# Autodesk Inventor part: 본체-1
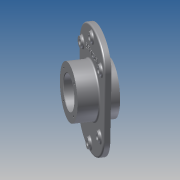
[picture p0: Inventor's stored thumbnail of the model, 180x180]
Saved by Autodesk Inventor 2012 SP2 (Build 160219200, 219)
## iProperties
Created: 2015-02
Part Number: 본체-1
Material: Default
Document SubType Name: Modeling
Designer: Administrator
Density: 1 g/cm^3
Author: Administrator
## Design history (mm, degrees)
sketch "스케치1"
  geometry: L1 (-70, 60)-(70, 60); L2 (70, 60)-(70, -60); L3 (70, -60)-(-70, -60); L4 (-70, -60)-(-70, 60); L5 (-70, 0)-(70, 0); L6 (0, 60)-(0, 110); L7 (0, -60)-(0, -110); 1 further point; 4 other entities
  constraints: 15 end point, 4 midpoint, 3 horizontal, 2 parallel, 2 vertical, 1 horizontal alignment, 1 perpendicular, 1 vertical alignment, 18 other
  dimensions: "d10" = 120 distance of L1.end L2.end; "d11" = 140 distance of L1.start L1.end; "d16" = 50 distance of L6.start L6.end
extrude "돌출1" new body sketch "스케치1" distance "d17" = 12; taper "d18" = 0 deg
sketch "스케치2"
  geometry: C1 r 50 at (0, 0); 1 further point
  constraints: 1 centre point, 1 coincident
  dimensions: "d19" = 100 diameter of C1
extrude "돌출2" join sketch "스케치2" distance "d20" = 37; taper "d22" = 0 deg; dims "d21" = 33, "d23" = 0
hole "구멍1" diameter "d26" = 62; stored, may be unused: countersink angle "d30" = 90 deg, drill point angle "d32" = 0 deg; dims "d27" = 6, "d28" = 4, "d29" = 2, "d31" = 22, "d44" = 10, "d45" = 10
hole "구멍2" diameter "d35" = 62; stored, may be unused: countersink angle "d39" = 90 deg, drill point angle "d41" = 0 deg; dims "d36" = 6, "d37" = 4, "d38" = 2, "d40" = 22, "d42" = 10, "d43" = 10
hole "구멍3" diameter "d48" = 45; stored, may be unused: countersink angle "d52" = 90 deg, drill point angle "d54" = 118 deg; dims "d46" = 10, "d47" = 10, "d49" = 6, "d50" = 4, "d51" = 2, "d53" = 22
sketch "스케치3"
  geometry: L1 (60, -70)-(-60, -70) reference; L2 (-60, 70)-(60, 70) reference; L3 (60, -53)-(-60, -53); L4 (-60, 53)-(60, 53); C1 r 50 at (0, 0) reference; C2 r 10 at (-57.146, 53); C3 r 10 at (60, 53); C4 r 10 at (-57.146, -53); C5 r 10 at (60, -53); C6 r 10 at (93, 0); C7 r 10 at (-93, 0); 8 further points; 2 other entities
  constraints: 8 coincident, 6 centre point, 4 end point, 3 horizontal alignment, 3 parallel, 2 point on line, 1 vertical alignment, 10 other
  dimensions: "d55" = 17 distance between parallel lines of L2 L4; "d56" = 20 diameter of C2; "d57" = 20 diameter of C3; "d58" = 20 diameter of C4; "d59" = 20 diameter of C5; "d60" = 20 diameter of C6; "d61" = 20 diameter of C7
extrude "돌출3" join sketch "스케치3" distance "d62" = 5; taper "d63" = 0 deg
hole "구멍4" diameter "d66" = 11; stored, may be unused: countersink angle "d70" = 90 deg, drill point angle "d72" = 118 deg; dims "d64" = 10, "d65" = 10, "d67" = 6, "d68" = 4, "d69" = 2, "d71" = 22
hole "구멍5" diameter "d75" = 11; stored, may be unused: countersink angle "d79" = 90 deg, drill point angle "d81" = 118 deg; dims "d73" = 10, "d74" = 10, "d76" = 6, "d77" = 4, "d78" = 2, "d80" = 22
hole "구멍6" diameter "d84" = 11; stored, may be unused: countersink angle "d88" = 90 deg, drill point angle "d90" = 118 deg; dims "d82" = 10, "d83" = 10, "d85" = 6, "d86" = 4, "d87" = 2, "d89" = 22
hole "구멍7" diameter "d93" = 11; stored, may be unused: countersink angle "d97" = 90 deg, drill point angle "d99" = 118 deg; dims "d91" = 10, "d92" = 10, "d94" = 6, "d95" = 4, "d96" = 2, "d98" = 22
hole "구멍8" diameter "d102" = 11; stored, may be unused: countersink angle "d106" = 90 deg, drill point angle "d108" = 118 deg; dims "d100" = 10, "d101" = 10, "d103" = 6, "d104" = 4, "d105" = 2, "d107" = 22
hole "구멍9" diameter "d111" = 11; stored, may be unused: countersink angle "d115" = 90 deg, drill point angle "d117" = 118 deg; dims "d109" = 10, "d110" = 10, "d112" = 6, "d113" = 4, "d114" = 2, "d116" = 22
sketch "스케치4"
  geometry: L1 (0, 0)-(41, 0); L2 (0, 0)-(28.991, -28.991); L3 (0, 0)-(28.991, 28.991); L4 (0, 0)-(-28.991, 28.991); L5 (0, 0)-(-28.991, -28.991); C1 r 31 at (0, 0) reference; A1 r 41 centre (0, 0) between (41, 0) and (28.991, -28.991); 4 further points
  constraints: 10 end point, 5 coincident, 2 point on circle, 1 centre point, 1 horizontal, 17 other
  dimensions: "d118" = 82 diameter of A1; "d119" = 45 deg angle of L1 L2; "d122" = 360 deg dimension on C1.centre L2.end (derived)
hole "구멍10" sketch "스케치4" at (28.991, -28.991), (28.991, 28.991), (-28.991, 28.991), (-28.991, -28.991) diameter "d124" = 4.917; stored, may be unused: countersink angle "d128" = 90 deg, drill point angle "d130" = 118 deg; dims "d125" = 10, "d126" = 4, "d127" = 2, "d129" = 13
sketch "스케치5"
  geometry: L1 (0, 0)-(-41, 0); L2 (0, 0)-(-28.991, -28.991); L3 (0, 0)-(28.991, -28.991); L4 (0, 0)-(28.991, 28.991); L5 (0, 0)-(-28.991, 28.991); C1 r 31 at (0, 0) reference; A1 r 41 centre (0, 0) between (-41, 0) and (-28.991, -28.991); 4 further points
  constraints: 10 end point, 5 coincident, 2 point on circle, 1 centre point, 1 horizontal, 17 other
  dimensions: "d131" = 82 diameter of A1; "d132" = 45 deg angle of L2 L1; "d135" = 360 deg dimension on C1.centre L2.end (derived)
hole "구멍11" sketch "스케치5" at (-28.991, -28.991), (28.991, -28.991), (28.991, 28.991), (-28.991, 28.991) diameter "d137" = 4.917; stored, may be unused: countersink angle "d141" = 90 deg, drill point angle "d143" = 118 deg; dims "d138" = 10, "d139" = 4, "d140" = 2, "d142" = 13
fillet "모깎기1" dims "d144" = 3
chamfer "모따기1" distance "d145" = 1; stored, may be unused: second distance "d146" = 2, angle "d147" = 45 deg
fillet "모깎기2" dims "d148" = 0.3
sketch "스케치6"
  geometry: C1 r 13 at (93, 0) reference; C2 r 53 at (0, 0) reference; 1 further point
  constraints: 1 horizontal alignment, 1 other
  dimensions: "d149" = 65 distance of point (65, 0) C2.centre
feature "엠보싱1" sketch "스케치6" dims "d10" = 120, "d40" = 22, "d150" = 1, "d151" = 0
node "솔리드1"
